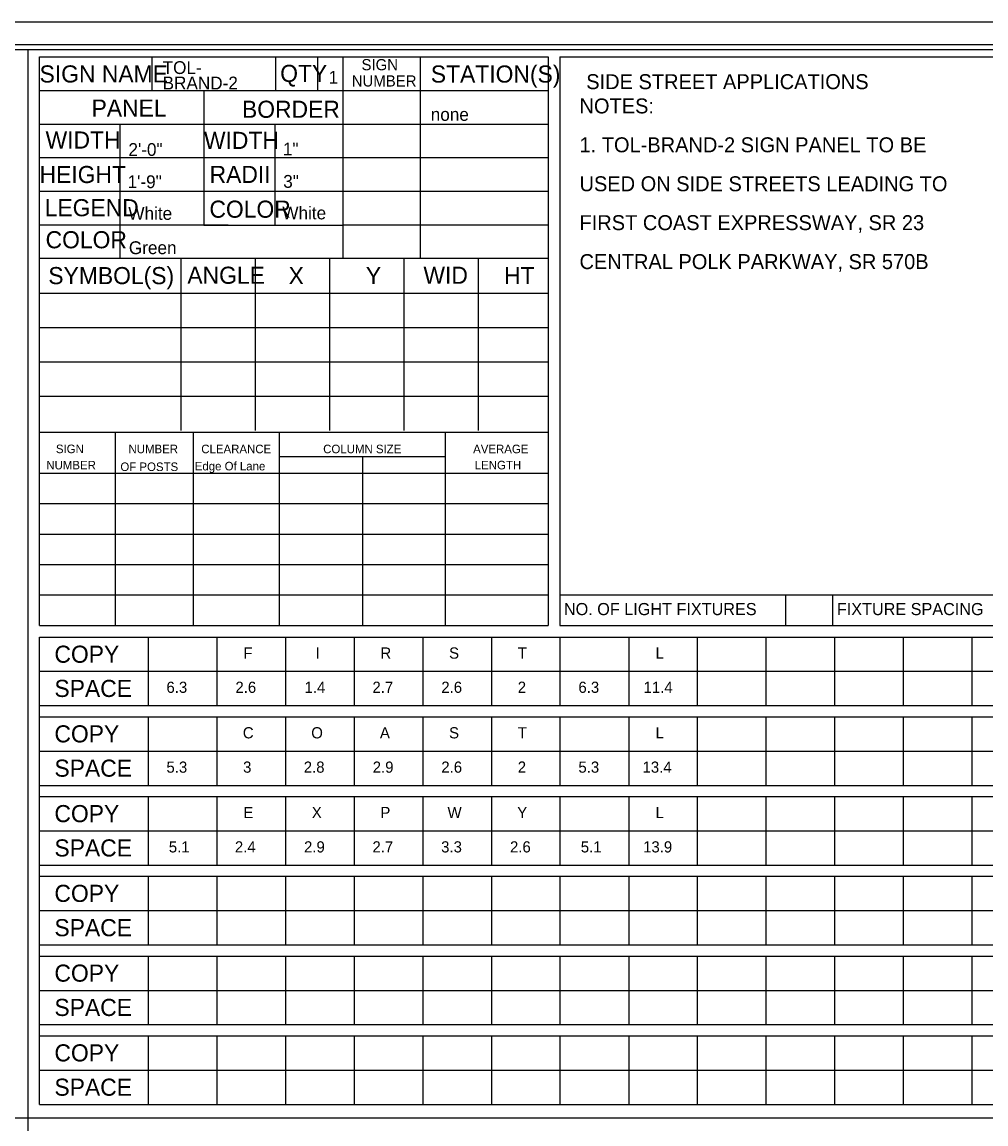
# Model space of a CAD drawing. Extents: x 17890628 to 17890754, y 17897693 to 17897992.
# Drawn here: x 17890707.16 to 17890717.72, y 17897888.7 to 17897900.78 of the extents above; entities that cross this region are included whole.
import ezdxf

# ---------------------------------------------------------------- set-up
doc = ezdxf.new("R2010")
doc.units = 0
for name, color, linetype in [('GSSign', 7, 'Continuous'), ('PlotBorder_dp', 7, 'Continuous'), ('SheetBorder_dp', 7, 'Continuous'), ('SheetLinesMisc2_dp', 7, 'Continuous'), ('TextMinor', 7, 'Continuous'), ('TextMisc', 7, 'Continuous')]:
    doc.layers.add(name, color=color, linetype=linetype)

msp = doc.modelspace()

# ---------------------------------------------------------------- linework, layer by layer
at = {"layer": 'PlotBorder_dp'}
msp.add_lwpolyline([(17890687.002, 17897874.814), (17890727.417, 17897874.814), (17890727.417, 17897900.777), (17890687.002, 17897900.777)], close=True, dxfattribs=at)
at = {"layer": 'SheetBorder_dp'}
msp.add_line((17890688.35, 17897900.533), (17890726.07, 17897900.533), dxfattribs=at)
at = {"layer": 'SheetLinesMisc2_dp'}
for p, q in [((17890688.417, 17897900.475), (17890726.026, 17897900.475)), ((17890707.222, 17897900.475), (17890707.222, 17897877.063)), ((17890707.35, 17897894.166), (17890707.35, 17897900.397)), ((17890707.35, 17897900.397), (17890712.927, 17897900.397)), ((17890708.579, 17897900.397), (17890708.579, 17897900.029)), ((17890709.935, 17897900.397), (17890709.935, 17897900.029)), ((17890710.398, 17897900.397), (17890710.398, 17897900.029)), ((17890710.674, 17897900.397), (17890710.674, 17897898.188)), ((17890711.522, 17897900.397), (17890711.522, 17897898.188)), ((17890712.927, 17897900.397), (17890712.927, 17897894.166)), ((17890713.055, 17897900.397), (17890725.847, 17897900.397)), ((17890713.055, 17897900.397), (17890713.055, 17897894.166)), ((17890707.35, 17897900.029), (17890712.927, 17897900.029)), ((17890709.152, 17897900.029), (17890709.152, 17897898.552)), ((17890707.35, 17897899.66), (17890712.927, 17897899.66)), ((17890708.231, 17897899.66), (17890708.231, 17897898.188)), ((17890709.93, 17897899.657), (17890709.93, 17897898.552)), ((17890707.35, 17897899.292), (17890712.927, 17897899.292)), ((17890707.35, 17897898.924), (17890712.927, 17897898.924)), ((17890707.35, 17897898.556), (17890709.418, 17897898.556)), ((17890709.152, 17897898.552), (17890710.674, 17897898.552)), ((17890710.674, 17897898.556), (17890712.927, 17897898.556)), ((17890707.35, 17897898.188), (17890712.927, 17897898.188)), ((17890708.899, 17897898.181), (17890708.899, 17897896.302)), ((17890709.714, 17897898.181), (17890709.714, 17897896.302)), ((17890710.528, 17897898.181), (17890710.528, 17897896.302)), ((17890711.343, 17897898.181), (17890711.343, 17897896.302)), ((17890712.158, 17897898.181), (17890712.158, 17897896.302)), ((17890707.351, 17897897.805), (17890712.927, 17897897.805)), ((17890707.351, 17897897.429), (17890712.927, 17897897.429)), ((17890707.351, 17897897.054), (17890712.927, 17897897.054)), ((17890707.351, 17897896.678), (17890712.927, 17897896.678)), ((17890707.35, 17897896.284), (17890712.927, 17897896.284)), ((17890708.178, 17897896.284), (17890708.178, 17897894.166)), ((17890709.033, 17897896.284), (17890709.033, 17897894.166)), ((17890709.977, 17897896.284), (17890709.977, 17897894.166)), ((17890711.796, 17897896.284), (17890711.796, 17897894.166)), ((17890709.977, 17897896.015), (17890711.795, 17897896.015)), ((17890710.89, 17897896.015), (17890710.89, 17897894.166)), ((17890707.35, 17897895.835), (17890712.927, 17897895.835)), ((17890707.35, 17897895.501), (17890712.927, 17897895.501)), ((17890707.35, 17897895.167), (17890712.927, 17897895.167)), ((17890707.35, 17897894.834), (17890712.927, 17897894.834)), ((17890707.35, 17897894.5), (17890712.927, 17897894.5)), ((17890713.055, 17897894.5), (17890725.847, 17897894.5)), ((17890715.526, 17897894.5), (17890715.526, 17897894.166)), ((17890716.044, 17897894.5), (17890716.044, 17897894.166)), ((17890707.35, 17897894.166), (17890712.927, 17897894.166)), ((17890713.055, 17897894.166), (17890725.847, 17897894.166)), ((17890707.35, 17897888.916), (17890707.35, 17897894.038)), ((17890707.35, 17897894.038), (17890725.847, 17897894.038)), ((17890708.541, 17897894.038), (17890708.541, 17897893.286)), ((17890709.293, 17897894.038), (17890709.293, 17897893.286)), ((17890710.046, 17897894.038), (17890710.046, 17897893.286)), ((17890710.798, 17897894.038), (17890710.798, 17897893.286)), ((17890711.551, 17897894.038), (17890711.551, 17897893.286)), ((17890712.303, 17897894.038), (17890712.303, 17897893.286)), ((17890713.055, 17897894.038), (17890713.055, 17897893.286)), ((17890713.808, 17897894.038), (17890713.808, 17897893.286)), ((17890714.56, 17897894.038), (17890714.56, 17897893.286)), ((17890715.313, 17897894.038), (17890715.313, 17897893.286)), ((17890716.065, 17897894.038), (17890716.065, 17897893.286)), ((17890716.817, 17897894.038), (17890716.817, 17897893.286)), ((17890717.57, 17897894.038), (17890717.57, 17897893.286)), ((17890707.35, 17897893.662), (17890725.847, 17897893.662)), ((17890707.35, 17897893.286), (17890725.847, 17897893.286)), ((17890707.35, 17897893.163), (17890725.847, 17897893.163)), ((17890708.541, 17897893.163), (17890708.541, 17897892.412)), ((17890709.293, 17897893.163), (17890709.293, 17897892.412)), ((17890710.046, 17897893.163), (17890710.046, 17897892.412)), ((17890710.798, 17897893.163), (17890710.798, 17897892.412)), ((17890711.551, 17897893.163), (17890711.551, 17897892.412)), ((17890712.303, 17897893.163), (17890712.303, 17897892.412)), ((17890713.055, 17897893.163), (17890713.055, 17897892.412)), ((17890713.808, 17897893.163), (17890713.808, 17897892.412)), ((17890714.56, 17897893.163), (17890714.56, 17897892.412)), ((17890715.313, 17897893.163), (17890715.313, 17897892.412)), ((17890716.065, 17897893.163), (17890716.065, 17897892.412)), ((17890716.817, 17897893.163), (17890716.817, 17897892.412)), ((17890717.57, 17897893.163), (17890717.57, 17897892.412)), ((17890707.35, 17897892.788), (17890725.847, 17897892.788)), ((17890707.35, 17897892.412), (17890725.847, 17897892.412)), ((17890707.35, 17897892.29), (17890725.847, 17897892.29)), ((17890708.541, 17897892.29), (17890708.541, 17897891.538)), ((17890709.293, 17897892.29), (17890709.293, 17897891.538)), ((17890710.046, 17897892.29), (17890710.046, 17897891.538)), ((17890710.798, 17897892.29), (17890710.798, 17897891.538)), ((17890711.551, 17897892.29), (17890711.551, 17897891.538)), ((17890712.303, 17897892.29), (17890712.303, 17897891.538)), ((17890713.055, 17897892.29), (17890713.055, 17897891.538)), ((17890713.808, 17897892.29), (17890713.808, 17897891.538)), ((17890714.56, 17897892.29), (17890714.56, 17897891.538)), ((17890715.313, 17897892.29), (17890715.313, 17897891.538)), ((17890716.065, 17897892.29), (17890716.065, 17897891.538)), ((17890716.817, 17897892.29), (17890716.817, 17897891.538)), ((17890717.57, 17897892.29), (17890717.57, 17897891.538)), ((17890707.35, 17897891.914), (17890725.847, 17897891.914)), ((17890707.35, 17897891.538), (17890725.847, 17897891.538)), ((17890707.35, 17897891.416), (17890725.847, 17897891.416)), ((17890708.541, 17897891.416), (17890708.541, 17897890.664)), ((17890709.293, 17897891.416), (17890709.293, 17897890.664)), ((17890710.046, 17897891.416), (17890710.046, 17897890.664)), ((17890710.798, 17897891.416), (17890710.798, 17897890.664)), ((17890711.551, 17897891.416), (17890711.551, 17897890.664)), ((17890712.303, 17897891.416), (17890712.303, 17897890.664)), ((17890713.055, 17897891.416), (17890713.055, 17897890.664)), ((17890713.808, 17897891.416), (17890713.808, 17897890.664)), ((17890714.56, 17897891.416), (17890714.56, 17897890.664)), ((17890715.313, 17897891.416), (17890715.313, 17897890.664)), ((17890716.065, 17897891.416), (17890716.065, 17897890.664)), ((17890716.817, 17897891.416), (17890716.817, 17897890.664)), ((17890717.57, 17897891.416), (17890717.57, 17897890.664)), ((17890707.35, 17897891.04), (17890725.847, 17897891.04)), ((17890707.35, 17897890.664), (17890725.847, 17897890.664)), ((17890707.35, 17897890.542), (17890725.847, 17897890.542)), ((17890708.541, 17897890.542), (17890708.541, 17897889.79)), ((17890709.293, 17897890.542), (17890709.293, 17897889.79)), ((17890710.046, 17897890.542), (17890710.046, 17897889.79)), ((17890710.798, 17897890.542), (17890710.798, 17897889.79)), ((17890711.551, 17897890.542), (17890711.551, 17897889.79)), ((17890712.303, 17897890.542), (17890712.303, 17897889.79)), ((17890713.055, 17897890.542), (17890713.055, 17897889.79)), ((17890713.808, 17897890.542), (17890713.808, 17897889.79)), ((17890714.56, 17897890.542), (17890714.56, 17897889.79)), ((17890715.313, 17897890.542), (17890715.313, 17897889.79)), ((17890716.065, 17897890.542), (17890716.065, 17897889.79)), ((17890716.817, 17897890.542), (17890716.817, 17897889.79)), ((17890717.57, 17897890.542), (17890717.57, 17897889.79)), ((17890707.35, 17897890.166), (17890725.847, 17897890.166)), ((17890707.35, 17897889.79), (17890725.847, 17897889.79)), ((17890707.35, 17897889.668), (17890725.847, 17897889.668)), ((17890708.541, 17897889.668), (17890708.541, 17897888.916)), ((17890709.293, 17897889.668), (17890709.293, 17897888.916)), ((17890710.046, 17897889.668), (17890710.046, 17897888.916)), ((17890710.798, 17897889.668), (17890710.798, 17897888.916)), ((17890711.551, 17897889.668), (17890711.551, 17897888.916)), ((17890712.303, 17897889.668), (17890712.303, 17897888.916)), ((17890713.055, 17897889.668), (17890713.055, 17897888.916)), ((17890713.808, 17897889.668), (17890713.808, 17897888.916)), ((17890714.56, 17897889.668), (17890714.56, 17897888.916)), ((17890715.313, 17897889.668), (17890715.313, 17897888.916)), ((17890716.065, 17897889.668), (17890716.065, 17897888.916)), ((17890716.817, 17897889.668), (17890716.817, 17897888.916)), ((17890717.57, 17897889.668), (17890717.57, 17897888.916)), ((17890707.35, 17897889.292), (17890725.847, 17897889.292)), ((17890707.35, 17897888.916), (17890725.847, 17897888.916)), ((17890688.417, 17897888.769), (17890726.026, 17897888.769))]:
    msp.add_line(p, q, dxfattribs=at)

# ---------------------------------------------------------------- texts
at = {"layer": 'GSSign'}
for s, height, p in [('TOL-', 0.1405, (17890708.699, 17897900.208)), ('1', 0.141, (17890710.518, 17897900.101)), ('BRAND-2', 0.1405, (17890708.699, 17897900.039)), ('none', 0.1406, (17890711.638, 17897899.695)), ('2\'-0"', 0.1406, (17890708.324, 17897899.31)), ('1"', 0.1406, (17890710.017, 17897899.315)), ('1\'-9"', 0.1406, (17890708.315, 17897898.957)), ('3"', 0.1406, (17890710.021, 17897898.961)), ('White', 0.1406, (17890708.323, 17897898.61)), ('White', 0.1406, (17890710.011, 17897898.615)), ('Green', 0.1406, (17890708.329, 17897898.234)), ('F', 0.123, (17890709.584, 17897893.801)), ('I', 0.123, (17890710.375, 17897893.801)), ('R', 0.123, (17890711.086, 17897893.801)), ('S', 0.123, (17890711.839, 17897893.801)), ('T', 0.123, (17890712.592, 17897893.801)), ('L', 0.123, (17890714.103, 17897893.801)), ('6.3', 0.1225, (17890708.741, 17897893.426)), ('2.6', 0.1225, (17890709.497, 17897893.426)), ('1.4', 0.1225, (17890710.255, 17897893.426)), ('2.7', 0.1225, (17890710.999, 17897893.426)), ('2.6', 0.1225, (17890711.754, 17897893.426)), ('2', 0.123, (17890712.592, 17897893.426)), ('6.3', 0.1225, (17890713.257, 17897893.426)), ('11.4', 0.1225, (17890713.971, 17897893.426)), ('C', 0.123, (17890709.578, 17897892.927)), ('O', 0.123, (17890710.328, 17897892.927)), ('A', 0.123, (17890711.081, 17897892.927)), ('S', 0.123, (17890711.839, 17897892.927)), ('T', 0.123, (17890712.592, 17897892.927)), ('L', 0.123, (17890714.103, 17897892.927)), ('5.3', 0.1225, (17890708.741, 17897892.551)), ('3', 0.123, (17890709.581, 17897892.551)), ('2.8', 0.1225, (17890710.246, 17897892.551)), ('2.9', 0.1225, (17890711.002, 17897892.551)), ('2.6', 0.1225, (17890711.754, 17897892.551)), ('2', 0.123, (17890712.592, 17897892.551)), ('5.3', 0.1225, (17890713.257, 17897892.551)), ('13.4', 0.1225, (17890713.96, 17897892.551)), ('E', 0.123, (17890709.584, 17897892.053)), ('X', 0.123, (17890710.334, 17897892.053)), ('P', 0.123, (17890711.086, 17897892.053)), ('W', 0.123, (17890711.822, 17897892.053)), ('Y', 0.123, (17890712.586, 17897892.053)), ('L', 0.123, (17890714.103, 17897892.053)), ('5.1', 0.1225, (17890708.767, 17897891.677)), ('2.4', 0.1225, (17890709.491, 17897891.677)), ('2.9', 0.1225, (17890710.249, 17897891.677)), ('2.7', 0.1225, (17890710.999, 17897891.677)), ('3.3', 0.1225, (17890711.752, 17897891.677)), ('2.6', 0.1225, (17890712.507, 17897891.677)), ('5.1', 0.1225, (17890713.283, 17897891.677)), ('13.9', 0.1225, (17890713.966, 17897891.677))]:
    msp.add_text(s, height=height, dxfattribs=at).set_placement(p)
at = {"layer": 'TextMinor'}
for s, height, p in [('SIGN', 0.1225, (17890710.879, 17897900.249)), ('SIGN NAME', 0.1875, (17890707.35, 17897900.115)), ('QTY', 0.1875, (17890709.988, 17897900.121)), ('STATION(S)', 0.1875, (17890711.639, 17897900.114)), ('NUMBER', 0.1225, (17890710.772, 17897900.071)), ('PANEL', 0.1875, (17890707.92, 17897899.741)), ('BORDER', 0.1875, (17890709.569, 17897899.728)), ('WIDTH', 0.1875, (17890707.416, 17897899.391)), ('WIDTH', 0.1875, (17890709.152, 17897899.387)), ('HEIGHT', 0.1875, (17890707.35, 17897899.013)), ('RADII', 0.1875, (17890709.214, 17897899.014)), ('LEGEND', 0.1875, (17890707.406, 17897898.649)), ('COLOR', 0.1875, (17890709.212, 17897898.633)), ('COLOR', 0.1875, (17890707.416, 17897898.298)), ('SYMBOL(S)', 0.1875, (17890707.446, 17897897.905)), ('ANGLE', 0.1875, (17890708.97, 17897897.909)), ('X', 0.187, (17890710.08, 17897897.905)), ('Y', 0.187, (17890710.927, 17897897.905)), ('WID', 0.1875, (17890711.558, 17897897.909)), ('HT', 0.1875, (17890712.442, 17897897.905)), ('SIGN', 0.0937, (17890707.529, 17897896.053)), ('NUMBER', 0.0937, (17890708.325, 17897896.052)), ('CLEARANCE', 0.0937, (17890709.123, 17897896.052)), ('COLUMN SIZE', 0.09374, (17890710.459, 17897896.052)), ('AVERAGE', 0.0937, (17890712.103, 17897896.052)), ('NUMBER', 0.0937, (17890707.424, 17897895.875)), ('OF POSTS', 0.0937, (17890708.236, 17897895.857)), ('Edge Of Lane', 0.09374, (17890709.051, 17897895.864)), ('LENGTH', 0.0937, (17890712.121, 17897895.875)), ('NO. OF LIGHT FIXTURES', 0.13286, (17890713.098, 17897894.278)), ('FIXTURE SPACING', 0.13286, (17890716.09, 17897894.278)), ('COPY', 0.1875, (17890707.513, 17897893.756)), ('SPACE', 0.1875, (17890707.513, 17897893.381)), ('COPY', 0.1875, (17890707.513, 17897892.883)), ('SPACE', 0.1875, (17890707.513, 17897892.507)), ('COPY', 0.1875, (17890707.513, 17897892.009)), ('SPACE', 0.1875, (17890707.513, 17897891.633)), ('COPY', 0.1875, (17890707.513, 17897891.135)), ('SPACE', 0.1875, (17890707.513, 17897890.759)), ('COPY', 0.1875, (17890707.513, 17897890.261)), ('SPACE', 0.1875, (17890707.513, 17897889.885)), ('COPY', 0.1875, (17890707.513, 17897889.387)), ('SPACE', 0.1875, (17890707.513, 17897889.011))]:
    msp.add_text(s, height=height, dxfattribs=at).set_placement(p)
at = {"layer": 'TextMisc'}
for s, p in [('SIDE STREET APPLICATIONS', (17890713.343, 17897900.042)), ('NOTES:', (17890713.269, 17897899.776)), ('1. TOL-BRAND-2 SIGN PANEL TO BE', (17890713.269, 17897899.35)), ('USED ON SIDE STREETS LEADING TO', (17890713.269, 17897898.923)), ('FIRST COAST EXPRESSWAY, SR 23', (17890713.269, 17897898.497)), ('CENTRAL POLK PARKWAY, SR 570B', (17890713.269, 17897898.07))]:
    msp.add_text(s, height=0.164, dxfattribs=at).set_placement(p)

doc.saveas('drawing.dxf')
